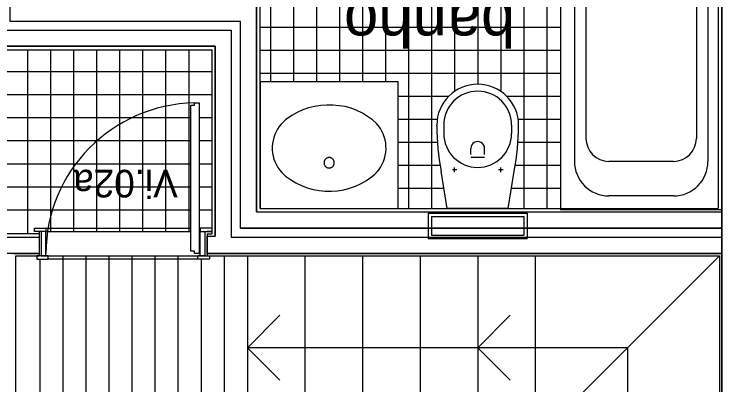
# Model space of a CAD drawing. Extents: x 1278 to 1356, y -253.7 to -224.
# Drawn here: x 1336.931 to 1340.025, y -240.985 to -239.375 of the extents above; entities that cross this region are included whole.
import ezdxf

# ---------------------------------------------------------------- set-up
doc = ezdxf.new("R2010")
doc.units = 0
for name, color, linetype in [('Level 1', 7, 'Continuous'), ('Level 10', 7, 'Continuous'), ('Level 11', 7, 'Continuous'), ('Level 13', 7, 'Continuous'), ('Level 2', 7, 'Continuous'), ('Level 4', 7, 'Continuous'), ('Level 40', 7, 'Continuous'), ('Level 60', 7, 'Continuous'), ('Level 65', 7, 'Continuous'), ('Level 66', 7, 'Continuous'), ('Level 67', 7, 'Continuous')]:
    doc.layers.add(name, color=color, linetype=linetype)

msp = doc.modelspace()

# ---------------------------------------------------------------- linework, layer by layer
at = {"layer": 'Level 1'}
for p, q in [((1340.0033, -238.614), (1340.0033, -240.234)), ((1337.9833, -240.234), (1337.9833, -239.3357)), ((1337.9133, -239.4057), (1336.9133, -239.4057)), ((1337.9133, -240.304), (1337.9133, -239.4057)), ((1336.8733, -239.444), (1337.8733, -239.444)), ((1337.8733, -239.444), (1337.8733, -240.344)), ((1336.8033, -239.514), (1337.8033, -239.514)), ((1337.8033, -239.514), (1337.8033, -240.339)), ((1337.0383, -240.319), (1337.0383, -240.424)), ((1337.7683, -240.329), (1337.7683, -240.424)), ((1337.8733, -240.344), (1340.0033, -240.344)), ((1336.9283, -240.414), (1337.0383, -240.414)), ((1337.7683, -240.414), (1340.0033, -240.414)), ((1340.0033, -240.414), (1340.0033, -242.034))]:
    msp.add_line(p, q, dxfattribs=at)
at = {"layer": 'Level 10'}
for p, q in [((1338.0433, -238.5207), (1338.0433, -239.669)), ((1338.1433, -238.5207), (1338.1433, -239.669)), ((1338.2433, -238.5207), (1338.2433, -239.669)), ((1338.3433, -238.5207), (1338.3433, -239.669)), ((1338.4433, -238.5207), (1338.4433, -239.669)), ((1338.5433, -238.629), (1338.5433, -239.669)), ((1338.6433, -238.629), (1338.6433, -240.219)), ((1338.7433, -238.629), (1338.7433, -240.219)), ((1339.1433, -238.629), (1339.1433, -240.219)), ((1339.2433, -238.629), (1339.2433, -240.219)), ((1338.8433, -239.1391), (1338.8433, -239.7067)), ((1339.0433, -239.1468), (1339.0433, -239.7067)), ((1338.9433, -239.1739), (1338.9433, -239.6759)), ((1337.9983, -239.4307), (1339.3033, -239.4307)), ((1336.9883, -239.529), (1336.9883, -240.329)), ((1337.0883, -239.529), (1337.0883, -240.319)), ((1337.1883, -239.529), (1337.1883, -240.319)), ((1337.2883, -239.529), (1337.2883, -240.319)), ((1337.3883, -239.529), (1337.3883, -240.319)), ((1337.4883, -239.529), (1337.4883, -240.319)), ((1337.5883, -239.529), (1337.5883, -240.319)), ((1337.6883, -239.529), (1337.6883, -240.319)), ((1337.9983, -239.5307), (1339.3033, -239.5307)), ((1335.5333, -239.624), (1337.7883, -239.624)), ((1337.9983, -239.6307), (1339.3033, -239.6307)), ((1336.0034, -239.724), (1337.7883, -239.724)), ((1338.5981, -239.7307), (1338.815, -239.7307)), ((1339.0716, -239.7307), (1339.3033, -239.7307)), ((1336.057, -239.824), (1337.6983, -239.824)), ((1337.7333, -239.824), (1337.7883, -239.824)), ((1338.5981, -239.8307), (1338.7672, -239.8307)), ((1339.1193, -239.8307), (1339.3033, -239.8307)), ((1336.0553, -239.924), (1337.6983, -239.924)), ((1337.7333, -239.924), (1337.7883, -239.924)), ((1338.5981, -239.9307), (1338.7684, -239.9307)), ((1339.1182, -239.9307), (1339.3033, -239.9307)), ((1336.0445, -240.024), (1337.6983, -240.024)), ((1337.7333, -240.024), (1337.7883, -240.024)), ((1338.5981, -240.0307), (1338.7802, -240.0307)), ((1339.1064, -240.0307), (1339.3033, -240.0307)), ((1336.0279, -240.124), (1337.6983, -240.124)), ((1337.7333, -240.124), (1337.7883, -240.124)), ((1338.5981, -240.1307), (1338.797, -240.1307)), ((1339.0896, -240.1307), (1339.3033, -240.1307)), ((1336.2883, -240.224), (1337.6983, -240.224)), ((1337.7333, -240.224), (1337.7883, -240.224)), ((1337.0683, -240.319), (1337.6983, -240.319)), ((1337.0433, -243.129), (1337.0433, -240.439)), ((1337.0783, -240.424), (1337.7283, -240.424)), ((1337.1433, -243.129), (1337.1433, -240.424)), ((1337.2433, -243.129), (1337.2433, -240.424)), ((1337.3433, -243.129), (1337.3433, -240.424)), ((1337.4433, -243.129), (1337.4433, -240.424)), ((1337.5433, -243.129), (1337.5433, -240.424)), ((1337.6433, -243.129), (1337.6433, -240.424)), ((1337.7433, -243.129), (1337.7433, -240.439)), ((1337.8433, -242.194), (1337.8433, -240.424))]:
    msp.add_line(p, q, dxfattribs=at)
at = {"layer": 'Level 11'}
for p, q in [((1339.3033, -238.624), (1339.3033, -240.224)), ((1340.0033, -238.624), (1340.0033, -240.224)), ((1339.3633, -238.964), (1339.3633, -240.014)), ((1339.4133, -238.964), (1339.4133, -239.914)), ((1339.8933, -238.964), (1339.8933, -239.914)), ((1339.9433, -238.964), (1339.9433, -240.014)), ((1338.184, -239.7905), (1338.1597, -239.8017)), ((1338.2092, -239.7816), (1338.184, -239.7905)), ((1338.2352, -239.7759), (1338.2092, -239.7816)), ((1338.2615, -239.7715), (1338.2352, -239.7759)), ((1338.2881, -239.7694), (1338.2615, -239.7715)), ((1338.3148, -239.7697), (1338.2881, -239.7694)), ((1338.3413, -239.7723), (1338.3148, -239.7697)), ((1338.3677, -239.7763), (1338.3413, -239.7723)), ((1338.3934, -239.7835), (1338.3677, -239.7763)), ((1338.4184, -239.793), (1338.3934, -239.7835)), ((1338.4424, -239.8047), (1338.4184, -239.793)), ((1338.1365, -239.8149), (1338.1094, -239.8341)), ((1338.1597, -239.8017), (1338.1365, -239.8149)), ((1338.4654, -239.8184), (1338.4424, -239.8047)), ((1338.4871, -239.8341), (1338.4654, -239.8184)), ((1338.0901, -239.8524), (1338.0817, -239.8628)), ((1338.0994, -239.8428), (1338.0901, -239.8524)), ((1338.1094, -239.8341), (1338.0994, -239.8428)), ((1338.5043, -239.85), (1338.4871, -239.8341)), ((1338.5129, -239.8602), (1338.5043, -239.85)), ((1338.5206, -239.8711), (1338.5129, -239.8602)), ((1338.7658, -239.8598), (1338.7658, -239.8562)), ((1338.7958, -239.8565), (1338.7958, -239.8926)), ((1339.0908, -239.8565), (1339.0908, -239.8926)), ((1339.1208, -239.8598), (1339.1208, -239.8562)), ((1338.0677, -239.8855), (1338.0622, -239.8977)), ((1338.0742, -239.8738), (1338.0677, -239.8855)), ((1338.0817, -239.8628), (1338.0742, -239.8738)), ((1338.5274, -239.8827), (1338.5206, -239.8711)), ((1338.5331, -239.8948), (1338.5274, -239.8827)), ((1338.0578, -239.9104), (1338.0545, -239.9234)), ((1338.0622, -239.8977), (1338.0578, -239.9104)), ((1338.5378, -239.9073), (1338.5331, -239.8948)), ((1338.5413, -239.9202), (1338.5378, -239.9073)), ((1338.5438, -239.9334), (1338.5413, -239.9202)), ((1338.0523, -239.9366), (1338.0513, -239.95)), ((1338.0513, -239.95), (1338.0514, -239.9638)), ((1338.0545, -239.9234), (1338.0523, -239.9366)), ((1338.5451, -239.9468), (1338.5438, -239.9334)), ((1338.5452, -239.9606), (1338.5451, -239.9468)), ((1338.0514, -239.9638), (1338.0527, -239.9784)), ((1338.0527, -239.9784), (1338.0552, -239.9916)), ((1338.542, -239.9885), (1338.5442, -239.9753)), ((1338.5442, -239.9753), (1338.5452, -239.9606)), ((1338.9133, -239.9845), (1338.9133, -239.9572)), ((1338.9733, -239.9845), (1338.9733, -239.9573)), ((1338.0552, -239.9916), (1338.0587, -240.0045)), ((1338.0587, -240.0045), (1338.0634, -240.0171)), ((1338.2767, -240.0143), (1338.2763, -240.0162)), ((1338.2773, -240.0124), (1338.2767, -240.0143)), ((1338.278, -240.0106), (1338.2773, -240.0124)), ((1338.2789, -240.0089), (1338.278, -240.0106)), ((1338.28, -240.0072), (1338.2789, -240.0089)), ((1338.2812, -240.0057), (1338.28, -240.0072)), ((1338.2825, -240.0042), (1338.2812, -240.0057)), ((1338.2839, -240.0029), (1338.2825, -240.0042)), ((1338.2855, -240.0017), (1338.2839, -240.0029)), ((1338.2871, -240.0006), (1338.2855, -240.0017)), ((1338.2888, -239.9997), (1338.2871, -240.0006)), ((1338.2906, -239.999), (1338.2888, -239.9997)), ((1338.2925, -239.9984), (1338.2906, -239.999)), ((1338.2944, -239.9979), (1338.2925, -239.9984)), ((1338.2963, -239.9977), (1338.2944, -239.9979)), ((1338.2983, -239.9976), (1338.2963, -239.9977)), ((1338.3002, -239.9977), (1338.2983, -239.9976)), ((1338.3021, -239.9979), (1338.3002, -239.9977)), ((1338.304, -239.9984), (1338.3021, -239.9979)), ((1338.3059, -239.999), (1338.304, -239.9984)), ((1338.3077, -239.9997), (1338.3059, -239.999)), ((1338.3094, -240.0006), (1338.3077, -239.9997)), ((1338.311, -240.0017), (1338.3094, -240.0006)), ((1338.3126, -240.0029), (1338.311, -240.0017)), ((1338.314, -240.0042), (1338.3126, -240.0029)), ((1338.3153, -240.0057), (1338.314, -240.0042)), ((1338.3165, -240.0072), (1338.3153, -240.0057)), ((1338.3176, -240.0089), (1338.3165, -240.0072)), ((1338.3185, -240.0106), (1338.3176, -240.0089)), ((1338.3192, -240.0124), (1338.3185, -240.0106)), ((1338.3198, -240.0143), (1338.3192, -240.0124)), ((1338.3202, -240.0162), (1338.3198, -240.0143)), ((1338.5288, -240.0263), (1338.5343, -240.0141)), ((1338.5343, -240.0141), (1338.5387, -240.0015)), ((1338.5387, -240.0015), (1338.542, -239.9885)), ((1338.9733, -239.9968), (1338.9133, -239.9968)), ((1339.7933, -240.014), (1339.5133, -240.014)), ((1338.0634, -240.0171), (1338.0691, -240.0292)), ((1338.0691, -240.0292), (1338.0759, -240.0407)), ((1338.0759, -240.0407), (1338.0836, -240.0516)), ((1338.276, -240.0182), (1338.2759, -240.0202)), ((1338.2759, -240.0202), (1338.276, -240.0221)), ((1338.2763, -240.0162), (1338.276, -240.0182)), ((1338.276, -240.0221), (1338.2763, -240.0241)), ((1338.2763, -240.0241), (1338.2767, -240.026)), ((1338.2767, -240.026), (1338.2773, -240.0279)), ((1338.2773, -240.0279), (1338.278, -240.0297)), ((1338.278, -240.0297), (1338.2789, -240.0314)), ((1338.2789, -240.0314), (1338.28, -240.0331)), ((1338.28, -240.0331), (1338.2812, -240.0347)), ((1338.2812, -240.0347), (1338.2825, -240.0361)), ((1338.2825, -240.0361), (1338.2839, -240.0374)), ((1338.2839, -240.0374), (1338.2855, -240.0386)), ((1338.2855, -240.0386), (1338.2871, -240.0397)), ((1338.2871, -240.0397), (1338.2888, -240.0406)), ((1338.2888, -240.0406), (1338.2906, -240.0414)), ((1338.2906, -240.0414), (1338.2925, -240.042)), ((1338.2925, -240.042), (1338.2944, -240.0424)), ((1338.2944, -240.0424), (1338.2963, -240.0426)), ((1338.2963, -240.0426), (1338.2983, -240.0427)), ((1338.2983, -240.0427), (1338.3002, -240.0426)), ((1338.3002, -240.0426), (1338.3021, -240.0424)), ((1338.3021, -240.0424), (1338.304, -240.042)), ((1338.304, -240.042), (1338.3059, -240.0414)), ((1338.3059, -240.0414), (1338.3077, -240.0406)), ((1338.3077, -240.0406), (1338.3094, -240.0397)), ((1338.3094, -240.0397), (1338.311, -240.0386)), ((1338.311, -240.0386), (1338.3126, -240.0374)), ((1338.3126, -240.0374), (1338.314, -240.0361)), ((1338.314, -240.0361), (1338.3153, -240.0347)), ((1338.3153, -240.0347), (1338.3165, -240.0331)), ((1338.3165, -240.0331), (1338.3176, -240.0314)), ((1338.3176, -240.0314), (1338.3185, -240.0297)), ((1338.3185, -240.0297), (1338.3192, -240.0279)), ((1338.3192, -240.0279), (1338.3198, -240.026)), ((1338.3198, -240.026), (1338.3202, -240.0241)), ((1338.3205, -240.0182), (1338.3202, -240.0162)), ((1338.3202, -240.0241), (1338.3205, -240.0221)), ((1338.3206, -240.0202), (1338.3205, -240.0182)), ((1338.3205, -240.0221), (1338.3206, -240.0202)), ((1338.5148, -240.0491), (1338.5223, -240.038)), ((1338.5223, -240.038), (1338.5288, -240.0263)), ((1338.8433, -240.0608), (1338.8433, -240.0408)), ((1339.0433, -240.0608), (1339.0433, -240.0408)), ((1338.0836, -240.0516), (1338.0922, -240.0618)), ((1338.0922, -240.0618), (1338.1094, -240.0778)), ((1338.4871, -240.0778), (1338.4971, -240.069)), ((1338.4971, -240.069), (1338.5064, -240.0595)), ((1338.5064, -240.0595), (1338.5148, -240.0491)), ((1338.811, -240.219), (1338.7843, -240.0569)), ((1338.8533, -240.0508), (1338.8333, -240.0508)), ((1339.0533, -240.0508), (1339.0333, -240.0508)), ((1339.0756, -240.219), (1339.1023, -240.0569)), ((1338.1094, -240.0778), (1338.1311, -240.0935)), ((1338.1311, -240.0935), (1338.1541, -240.1072)), ((1338.1541, -240.1072), (1338.1781, -240.1189)), ((1338.4368, -240.1102), (1338.46, -240.0969)), ((1338.46, -240.0969), (1338.4871, -240.0778)), ((1338.1781, -240.1189), (1338.2031, -240.1284)), ((1338.2031, -240.1284), (1338.229, -240.1356)), ((1338.229, -240.1356), (1338.2552, -240.1406)), ((1338.335, -240.1414), (1338.3615, -240.137)), ((1338.3615, -240.137), (1338.3873, -240.1303)), ((1338.3873, -240.1303), (1338.4125, -240.1213)), ((1338.4125, -240.1213), (1338.4368, -240.1102)), ((1338.2552, -240.1406), (1338.2817, -240.1432)), ((1338.2817, -240.1432), (1338.3084, -240.1435)), ((1338.3084, -240.1435), (1338.335, -240.1414)), ((1339.7933, -240.164), (1339.5133, -240.164)), ((1339.0756, -240.219), (1338.811, -240.219)), ((1340.0033, -240.224), (1339.3033, -240.224)), ((1338.7283, -240.239), (1338.7283, -240.349)), ((1338.7283, -240.239), (1339.1583, -240.239)), ((1338.7433, -240.254), (1339.1433, -240.254)), ((1338.7433, -240.254), (1338.7433, -240.334)), ((1339.1433, -240.254), (1339.1433, -240.334)), ((1339.1583, -240.239), (1339.1583, -240.349)), ((1338.7283, -240.349), (1339.1583, -240.349)), ((1338.7433, -240.334), (1339.1433, -240.334))]:
    msp.add_line(p, q, dxfattribs=at)
for centre, radius, start, end in [((1338.9433, -239.8565), 0.1775, 0.0002, 179.9999), ((1338.9433, -239.8565), 0.1475, 0.0002, 179.9999), ((1338.9433, -239.8926), 0.1475, 180.0002, 359.9999), ((1339.5133, -239.914), 0.1, 180.0001, 269.9999), ((1339.7933, -239.914), 0.1, 270, 0), ((1338.9433, -239.9574), 0.03, 359.9995, 180.0013), ((1339.5133, -240.014), 0.15, 179.9998, 270.0001), ((1339.7933, -240.014), 0.15, 270, 0)]:
    msp.add_arc(centre, radius, start, end, dxfattribs=at)
for centre, major_axis, start_param, end_param in [((1340.1658, -239.8598), (-1.4, 0), 6.283184, 6.446103), ((1337.7208, -239.8598), (1.4, 0), 6.120269, 6.283188)]:
    msp.add_ellipse(centre, major_axis=major_axis, ratio=0.867931, start_param=start_param, end_param=end_param, dxfattribs=at)
at = {"layer": 'Level 13'}
for p, q in [((1337.7133, -239.7597), (1337.7333, -239.7597)), ((1337.7133, -239.7697), (1337.7133, -239.76)), ((1337.7333, -239.7597), (1337.7333, -240.4147)), ((1337.6983, -240.4047), (1337.6983, -239.7697)), ((1337.6983, -239.7697), (1337.7133, -239.7697)), ((1337.0183, -240.304), (1337.0683, -240.304)), ((1337.0183, -240.319), (1337.0183, -240.304)), ((1337.0683, -240.319), (1337.0183, -240.319)), ((1337.0483, -240.319), (1337.0483, -240.424)), ((1337.0683, -240.319), (1337.0483, -240.319)), ((1337.0683, -240.304), (1337.0683, -240.319)), ((1337.0683, -240.424), (1337.0683, -240.319)), ((1337.7883, -240.304), (1337.7383, -240.304)), ((1337.7383, -240.304), (1337.7383, -240.319)), ((1337.7383, -240.424), (1337.7383, -240.319)), ((1337.7383, -240.319), (1337.7583, -240.319)), ((1337.7383, -240.319), (1337.7883, -240.319)), ((1337.7583, -240.319), (1337.7583, -240.424)), ((1337.7133, -240.4047), (1337.6983, -240.4047)), ((1337.7133, -240.4147), (1337.7133, -240.4047)), ((1337.7333, -240.4147), (1337.7133, -240.4147)), ((1337.0783, -240.424), (1337.0283, -240.424)), ((1337.0283, -240.424), (1337.0283, -240.439)), ((1337.0283, -240.439), (1337.0783, -240.439)), ((1337.0483, -240.424), (1337.0783, -240.424)), ((1337.0783, -240.439), (1337.0783, -240.424)), ((1337.7583, -240.424), (1337.7283, -240.424)), ((1337.7283, -240.424), (1337.7783, -240.424)), ((1337.7283, -240.439), (1337.7283, -240.424)), ((1337.7783, -240.439), (1337.7283, -240.439)), ((1337.7783, -240.424), (1337.7783, -240.439))]:
    msp.add_line(p, q, dxfattribs=at)
at = {"layer": 'Level 2'}
for p, q in [((1338.5981, -239.669), (1337.9983, -239.669)), ((1337.9983, -239.669), (1337.9983, -240.219)), ((1338.5981, -240.219), (1338.5981, -239.669)), ((1337.9433, -240.424), (1337.9433, -241.194)), ((1338.1933, -240.424), (1338.1933, -241.194)), ((1338.4433, -240.424), (1338.4433, -241.194)), ((1338.6933, -240.424), (1338.6933, -241.194)), ((1338.9433, -240.424), (1338.9433, -241.194)), ((1339.1933, -240.424), (1339.1933, -241.194)), ((1339.1933, -241.224), (1339.9933, -240.424)), ((1338.0847, -240.6826), (1337.9433, -240.824)), ((1339.0847, -240.6826), (1338.9433, -240.824)), ((1339.5933, -240.824), (1337.9433, -240.824)), ((1338.0847, -240.9654), (1337.9433, -240.824)), ((1339.5933, -240.824), (1338.9433, -240.824)), ((1339.0847, -240.9654), (1338.9433, -240.824)), ((1339.594, -240.824), (1338.944, -240.824)), ((1339.5933, -240.824), (1339.5933, -241.624))]:
    msp.add_line(p, q, dxfattribs=at)
at = {"layer": 'Level 4'}
for p, q in [((1337.0683, -240.304), (1337.6983, -240.304)), ((1337.7283, -240.439), (1337.0783, -240.439))]:
    msp.add_line(p, q, dxfattribs=at)
msp.add_ellipse((1337.7269, -240.4147), major_axis=(0.6586, 0), ratio=0.994279, start_param=1.591512, end_param=3.141593, dxfattribs=at)
at = {"layer": 'Level 65'}
for p, q in [((1339.9883, -238.629), (1339.9883, -240.219)), ((1337.9983, -240.219), (1337.9983, -239.3207)), ((1336.7883, -239.529), (1337.7883, -239.529)), ((1337.7883, -239.529), (1337.7883, -240.329)), ((1337.9983, -240.219), (1339.9883, -240.219)), ((1337.7883, -240.319), (1337.7683, -240.319)), ((1337.0383, -240.329), (1336.2883, -240.329)), ((1337.7683, -240.329), (1337.7883, -240.329)), ((1336.9383, -242.194), (1336.9383, -240.424)), ((1336.9383, -240.424), (1337.0383, -240.424)), ((1337.7783, -240.424), (1339.9933, -240.424)), ((1339.9933, -240.424), (1339.9933, -242.024))]:
    msp.add_line(p, q, dxfattribs=at)
at = {"layer": 'Level 66'}
for p, q in [((1337.9833, -240.234), (1340.0033, -240.234)), ((1337.9133, -240.304), (1340.0033, -240.304)), ((1340.0033, -240.304), (1340.0033, -240.3422)), ((1336.2733, -240.344), (1337.0383, -240.344)), ((1337.7683, -240.339), (1337.8033, -240.339))]:
    msp.add_line(p, q, dxfattribs=at)
at = {"layer": 'Level 67'}
for points in [[(1340.0033, -240.234), (1340.0033, -240.304), (1337.9133, -240.304), (1337.9133, -239.4057), (1336.9133, -239.4057), (1336.9133, -238.5057), (1335.7533, -238.5057), (1335.7533, -238.244), (1334.8332, -238.244), (1334.8333, -238.174), (1335.8241, -238.174), (1335.8241, -238.4357), (1336.8533, -238.4357), (1336.8533, -236.6557), (1336.9333, -236.6557), (1336.9333, -238.4357), (1337.022, -238.4357), (1337.0183, -238.4357), (1337.0183, -238.5057), (1336.9833, -238.5057), (1336.9833, -239.3357), (1337.9833, -239.3357), (1337.9833, -240.234), (1340.0033, -240.234)], [(1340.0733, -242.1713), (1340.0033, -242.1713), (1340.0033, -236.7713), (1340.0733, -236.7713)], [(1340.0033, -240.414), (1337.7683, -240.414), (1337.7683, -240.339), (1337.8033, -240.339), (1337.8033, -239.514), (1336.8033, -239.514), (1336.8033, -238.614), (1334.8333, -238.614), (1334.8333, -238.544), (1336.8733, -238.544), (1336.8733, -239.444), (1337.8733, -239.444), (1337.8733, -240.344), (1340.0033, -240.344)], [(1337.0383, -240.344), (1337.0383, -240.414), (1335.8233, -240.414), (1335.8233, -240.344)]]:
    msp.add_lwpolyline(points, close=True, dxfattribs=at)

# ---------------------------------------------------------------- texts
at = {"layer": 'Level 40'}
msp.add_text('Vi.02a', height=0.12, rotation=180, dxfattribs=at).set_placement((1337.6412, -240.0507))
at = {"layer": 'Level 60'}
msp.add_text('banho', height=0.2, rotation=180, dxfattribs=at).set_placement((1339.1067, -239.3132))

doc.saveas('drawing.dxf')
